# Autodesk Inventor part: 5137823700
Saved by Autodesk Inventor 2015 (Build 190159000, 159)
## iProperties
Created: 2020-07
Part Number: 5137823700
Checked By: TraceParts S.A.
Material: Generic
Catalog Web Link: www.traceparts.com
Document SubType Name: Modeling
Designer: TraceParts
Density: 1 g/cm^3
Appearance: Default
Company: TraceParts S.A.
Author: TraceParts
REFERENCE: 5137823700
DESIGN: CVAT/4-1400/250 N D PTC 0,18KW (230/400V) 50Hz - 5137823700
SUPPLIER: Soler & Palau
TraceParts.PartNumber: 10-14122018-105188
TraceParts.PartTitle: CVAT-N
TraceParts.InstanceId: 10-14122018-105188BS4GV9DP9WE543CAZWCVS9B80
TraceParts.PartStatus: Published
TraceParts.PartVersion: 1.0.4
TRACEPARTS: TRACEPARTS
TraceParts.PartLanguage: en
TraceParts.ClassPath: SOLER_PALAU:10-14122018-105188
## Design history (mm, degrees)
feature "5137823700"
body "Solid1"
